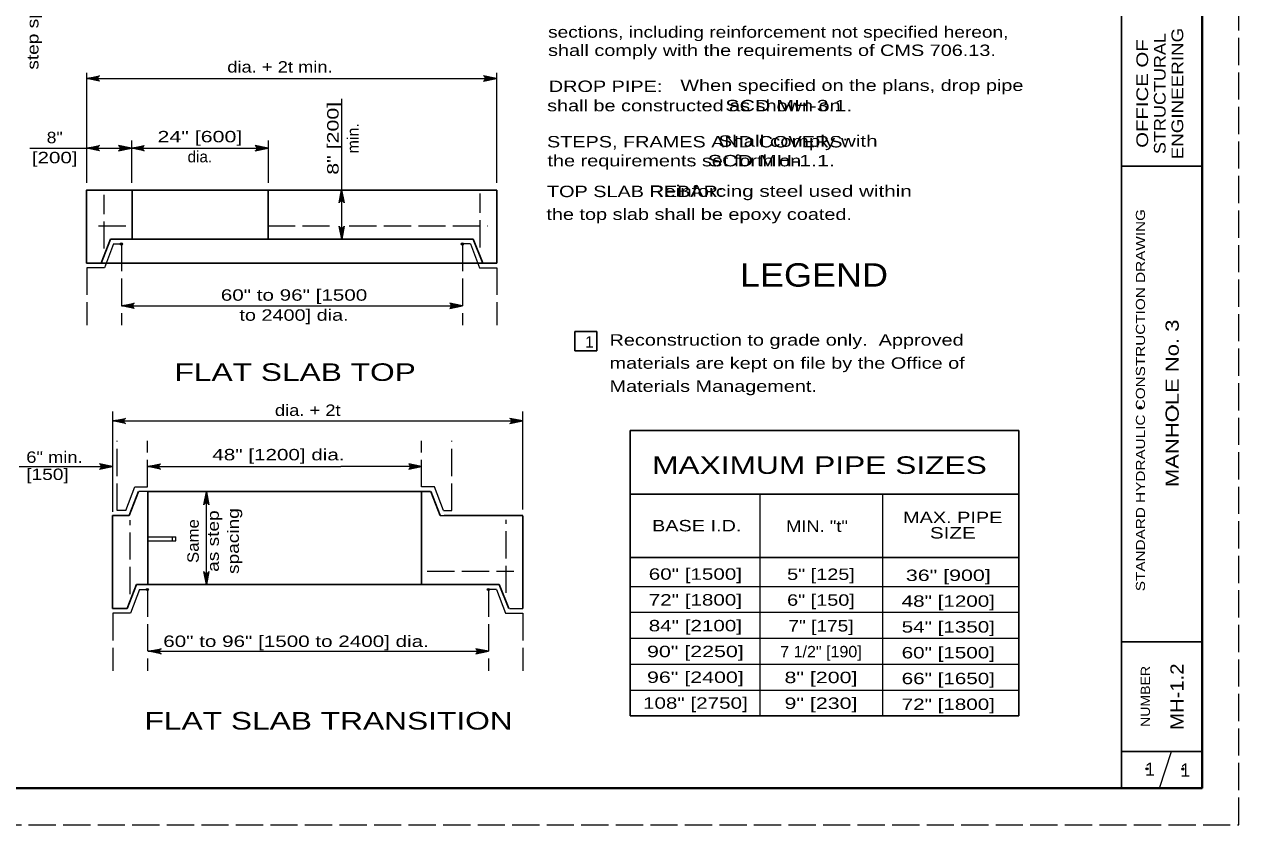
# Model space of a CAD drawing. Extents: x 808.4 to 842.4, y 1034.6 to 1056.6.
# Drawn here: x 825.84 to 842.44, y 1034.63 to 1045.57 of the extents above; entities that cross this region are included whole.
import ezdxf
from ezdxf.enums import TextEntityAlignment as Align

# ---------------------------------------------------------------- set-up
doc = ezdxf.new("R2010")
doc.units = 0
doc.header["$LTSCALE"] = 0.062
doc.header["$PDMODE"] = 32
doc.header["$PDSIZE"] = 0.031
doc.linetypes.add('LONG_DASHED', pattern=[7.5, 6, -1.5])
doc.layers.add('1', color=7, linetype='Continuous', lineweight=13)
doc.layers.add('10', color=7, linetype='Continuous')

msp = doc.modelspace()

# ---------------------------------------------------------------- linework, layer by layer
at = {"layer": '1', "lineweight": 25}
for p, q in [((840.83883, 1035.12767), (840.83883, 1056.12767)), ((841.93883, 1043.62767), (840.83883, 1043.62767)), ((827.31842, 1043.30192), (827.31842, 1042.64233)), ((829.17775, 1043.29608), (829.17775, 1042.6365)), ((832.30142, 1042.30433), (832.30142, 1043.30375)), ((827.0205, 1042.63308), (826.89208, 1042.30433)), ((827.0205, 1042.63308), (826.89208, 1042.30433)), ((827.0205, 1042.63308), (831.979, 1042.63308)), ((831.979, 1042.63308), (832.10733, 1042.30433)), ((826.69408, 1042.30433), (830.24717, 1042.30433)), ((830.24717, 1042.30433), (832.30142, 1042.30433)), ((834.12375, 1036.11517), (834.12375, 1040.01483)), ((834.12375, 1040.01483), (839.43508, 1040.01483)), ((839.43508, 1040.01483), (839.43508, 1036.11517)), ((827.27517, 1038.85458), (827.40358, 1039.18325)), ((827.5325, 1039.18325), (827.5325, 1038.624)), ((827.5325, 1039.18325), (828.22292, 1039.18325)), ((828.20442, 1039.18325), (831.39317, 1039.18325)), ((831.26942, 1039.18325), (831.26942, 1038.26033)), ((831.52533, 1038.85458), (831.397, 1039.18325)), ((834.12375, 1039.14483), (839.43508, 1039.14483)), ((827.27517, 1038.85458), (827.04642, 1038.85458)), ((827.04958, 1038.624), (827.04958, 1038.85533)), ((831.57933, 1038.85458), (832.65692, 1038.85458)), ((832.65692, 1038.624), (832.65692, 1038.85225)), ((827.04958, 1037.58108), (827.04958, 1038.66317)), ((827.5325, 1038.65608), (827.5325, 1037.91908)), ((832.65692, 1037.58108), (832.65692, 1038.624)), ((831.26942, 1038.28175), (831.26942, 1037.91908)), ((834.12517, 1038.2785), (839.43508, 1038.2785)), ((827.37592, 1037.90983), (827.24758, 1037.58108)), ((827.37592, 1037.90983), (827.24758, 1037.58108)), ((827.37592, 1037.90983), (832.33442, 1037.90983)), ((832.33442, 1037.90983), (832.46283, 1037.58108)), ((827.04958, 1037.58108), (827.25, 1037.58108)), ((841.93883, 1037.12767), (840.83883, 1037.12767)), ((834.12375, 1036.11517), (839.43508, 1036.11517)), ((841.93883, 1035.62767), (840.83883, 1035.62767))]:
    msp.add_line(p, q, dxfattribs=at)
at = {"layer": '1'}
for p, q in [((826.69433, 1044.907), (826.69433, 1043.4005)), ((832.29692, 1044.907), (832.29692, 1043.4005)), ((826.85308, 1044.85108), (826.69283, 1044.82867)), ((826.84767, 1044.83992), (826.69283, 1044.82867)), ((826.69283, 1044.82867), (830.56875, 1044.82867)), ((826.846, 1044.82867), (826.69283, 1044.82867)), ((826.84883, 1044.81425), (826.69283, 1044.82867)), ((826.85492, 1044.80383), (826.69283, 1044.82867)), ((830.56875, 1044.82867), (832.29692, 1044.82867)), ((832.13483, 1044.80383), (832.29692, 1044.82867)), ((832.13675, 1044.85108), (832.29692, 1044.82867)), ((832.141, 1044.81425), (832.29692, 1044.82867)), ((832.14217, 1044.83992), (832.29692, 1044.82867)), ((832.14375, 1044.82867), (832.29692, 1044.82867)), ((830.18075, 1042.63308), (830.18075, 1044.55125)), ((826.85483, 1043.89825), (826.69458, 1043.87583)), ((826.84933, 1043.88717), (826.69458, 1043.87583)), ((827.14617, 1043.898), (827.30642, 1043.87558)), ((827.15158, 1043.88692), (827.30642, 1043.87558)), ((827.30633, 1043.97975), (827.30633, 1043.4005)), ((827.46667, 1043.898), (827.30642, 1043.87558)), ((827.46125, 1043.88692), (827.30642, 1043.87558)), ((829.01467, 1043.898), (829.17483, 1043.8755)), ((829.02008, 1043.88683), (829.17483, 1043.8755)), ((829.17558, 1043.97975), (829.17558, 1043.4005)), ((825.91942, 1043.87558), (827.32025, 1043.87558)), ((826.84775, 1043.87583), (826.69458, 1043.87583)), ((826.85058, 1043.86142), (826.69458, 1043.87583)), ((826.85667, 1043.851), (826.69458, 1043.87583)), ((827.14433, 1043.85083), (827.30642, 1043.87558)), ((827.15042, 1043.86117), (827.30642, 1043.87558)), ((827.15325, 1043.87558), (827.30642, 1043.87558)), ((827.45958, 1043.87558), (827.30642, 1043.87558)), ((827.46242, 1043.86117), (827.30642, 1043.87558)), ((827.46858, 1043.85083), (827.30642, 1043.87558)), ((829.01275, 1043.85075), (829.17483, 1043.8755)), ((829.01892, 1043.86117), (829.17483, 1043.8755)), ((829.02167, 1043.8755), (829.17483, 1043.8755)), ((830.15517, 1043.1455), (830.18, 1043.30758)), ((830.16558, 1043.15167), (830.18, 1043.30758)), ((830.18, 1043.15442), (830.18, 1043.30758)), ((830.19133, 1043.15283), (830.18, 1043.30758)), ((830.20242, 1043.14742), (830.18, 1043.30758)), ((830.15833, 1042.79283), (830.18075, 1042.63258)), ((830.16942, 1042.78733), (830.18075, 1042.63258)), ((830.2055, 1042.79467), (830.18075, 1042.63258)), ((830.19517, 1042.78858), (830.18075, 1042.63258)), ((830.18075, 1042.78575), (830.18075, 1042.63258)), ((830.18075, 1042.63308), (830.18075, 1042.63258)), ((827.32967, 1041.74367), (827.16942, 1041.72125)), ((827.32417, 1041.73258), (827.16942, 1041.72125)), ((827.16942, 1041.72125), (830.75725, 1041.72125)), ((827.32258, 1041.72125), (827.16942, 1041.72125)), ((827.32542, 1041.70683), (827.16942, 1041.72125)), ((827.3315, 1041.6965), (827.16942, 1041.72125)), ((830.75725, 1041.72125), (831.83308, 1041.72125)), ((831.67092, 1041.6965), (831.83308, 1041.72125)), ((831.67283, 1041.74367), (831.83308, 1041.72125)), ((831.67708, 1041.70683), (831.83308, 1041.72125)), ((831.67825, 1041.73258), (831.83308, 1041.72125)), ((831.67992, 1041.72125), (831.83308, 1041.72125)), ((827.04975, 1040.27833), (827.04975, 1038.90517)), ((832.65242, 1040.27833), (832.65242, 1038.93592)), ((827.21, 1040.16908), (827.04975, 1040.14667)), ((827.20458, 1040.158), (827.04975, 1040.14667)), ((827.04975, 1040.14667), (830.62492, 1040.14667)), ((827.20292, 1040.14667), (827.04975, 1040.14667)), ((827.20575, 1040.13225), (827.04975, 1040.14667)), ((827.21192, 1040.12183), (827.04975, 1040.14667)), ((830.62492, 1040.14667), (832.65408, 1040.14667)), ((832.49192, 1040.12183), (832.65408, 1040.14667)), ((832.49383, 1040.16908), (832.65408, 1040.14667)), ((832.49808, 1040.13225), (832.65408, 1040.14667)), ((832.49925, 1040.158), (832.65408, 1040.14667)), ((832.50092, 1040.14667), (832.65408, 1040.14667)), ((825.77383, 1039.52317), (827.04975, 1039.52317)), ((826.88767, 1039.49842), (827.04975, 1039.52317)), ((826.8895, 1039.54558), (827.04975, 1039.52317)), ((826.89375, 1039.50875), (827.04975, 1039.52317)), ((826.895, 1039.5345), (827.04975, 1039.52317)), ((826.89658, 1039.52317), (827.04975, 1039.52317)), ((827.68767, 1039.54558), (827.52742, 1039.52317)), ((827.68225, 1039.5345), (827.52742, 1039.52317)), ((827.52742, 1039.52317), (830.16733, 1039.52317)), ((827.68058, 1039.52317), (827.52742, 1039.52317)), ((827.68342, 1039.50875), (827.52742, 1039.52317)), ((827.68958, 1039.49842), (827.52742, 1039.52317)), ((831.27308, 1039.52317), (830.16733, 1039.52317)), ((831.11092, 1039.49842), (831.27308, 1039.52317)), ((831.11283, 1039.54558), (831.27308, 1039.52317)), ((831.11708, 1039.50875), (831.27308, 1039.52317)), ((831.11825, 1039.5345), (831.27308, 1039.52317)), ((831.11992, 1039.52317), (831.27308, 1039.52317)), ((827.5325, 1039.18325), (827.4065, 1039.18325)), ((828.30658, 1039.01658), (828.33133, 1039.17867)), ((828.31692, 1039.02267), (828.33133, 1039.17867)), ((828.33133, 1037.90983), (828.33133, 1039.17867)), ((828.33133, 1039.0255), (828.33133, 1039.17867)), ((828.34267, 1039.02392), (828.33133, 1039.17867)), ((828.35375, 1039.0185), (828.33133, 1039.17867)), ((831.26808, 1039.18325), (831.39408, 1039.18325)), ((835.89375, 1039.13467), (835.89375, 1036.11517)), ((837.57075, 1039.13467), (837.57075, 1036.11517)), ((831.52533, 1038.85458), (831.75417, 1038.85458)), ((827.53442, 1038.563), (827.9125, 1038.563)), ((827.53442, 1038.51), (827.9125, 1038.51)), ((827.86875, 1038.50917), (827.86875, 1038.56217)), ((827.9125, 1038.51), (827.9125, 1038.563)), ((828.30892, 1038.07008), (828.33133, 1037.90983)), ((828.35608, 1038.072), (828.33133, 1037.90983)), ((828.32, 1038.06467), (828.33133, 1037.90983)), ((828.34575, 1038.06583), (828.33133, 1037.90983)), ((828.33133, 1038.063), (828.33133, 1037.90983)), ((834.12517, 1037.88517), (839.43508, 1037.88517)), ((832.4745, 1037.58108), (832.65692, 1037.58108)), ((834.12517, 1037.53117), (839.43508, 1037.53117)), ((834.12517, 1037.17717), (839.43508, 1037.17717)), ((827.69475, 1037.0205), (827.5345, 1036.99808)), ((827.68933, 1037.00933), (827.5345, 1036.99808)), ((827.5345, 1036.99808), (831.12242, 1036.99808)), ((827.68767, 1036.99808), (827.5345, 1036.99808)), ((827.6905, 1036.98367), (827.5345, 1036.99808)), ((827.69667, 1036.97325), (827.5345, 1036.99808)), ((831.12242, 1036.99808), (832.1885, 1036.99808)), ((832.02642, 1036.97325), (832.1885, 1036.99808)), ((832.02825, 1037.0205), (832.1885, 1036.99808)), ((832.0325, 1036.98367), (832.1885, 1036.99808)), ((832.03375, 1037.00933), (832.1885, 1036.99808)), ((832.03533, 1036.99808), (832.1885, 1036.99808)), ((834.12517, 1036.82317), (839.43508, 1036.82317)), ((834.12375, 1036.46917), (839.43508, 1036.46917)), ((834.12517, 1036.46917), (839.43508, 1036.46917)), ((841.3555, 1035.12767), (841.52217, 1035.62767))]:
    msp.add_line(p, q, dxfattribs=at)
at = {"layer": '1', "linetype": 'LONG_DASHED'}
for p, q in [((826.93425, 1042.50267), (826.93425, 1043.23833)), ((832.07308, 1042.51867), (832.07308, 1043.25425)), ((826.85767, 1042.81542), (827.317, 1042.81542)), ((829.17092, 1042.81542), (830.10125, 1042.81542)), ((830.28408, 1042.81542), (832.17917, 1042.81542)), ((827.06, 1042.56633), (826.93708, 1042.24142)), ((831.93942, 1042.56633), (831.83008, 1042.56633)), ((831.83008, 1042.56633), (831.83008, 1041.45425)), ((831.93942, 1042.56633), (832.06233, 1042.24142)), ((827.11375, 1038.92125), (827.11375, 1039.87725)), ((827.52742, 1039.24567), (827.52742, 1039.87725)), ((831.27308, 1039.24567), (831.27308, 1039.87725)), ((831.68683, 1038.92125), (831.68683, 1039.87725)), ((827.22958, 1038.92075), (827.35258, 1039.24567)), ((827.35258, 1039.24567), (827.52742, 1039.24567)), ((831.448, 1039.24567), (831.27308, 1039.24567)), ((831.57092, 1038.92075), (831.448, 1039.24567)), ((827.23067, 1038.92125), (827.11375, 1038.92125)), ((831.56992, 1038.92125), (831.68683, 1038.92125)), ((827.28975, 1037.77942), (827.28975, 1038.79158)), ((832.4285, 1037.79542), (832.4285, 1038.79517)), ((831.35017, 1038.09225), (832.53467, 1038.09225)), ((827.4155, 1037.84317), (827.29258, 1037.51825)), ((832.29492, 1037.84317), (832.1855, 1037.84317)), ((832.1855, 1037.84317), (832.1855, 1036.731)), ((832.29492, 1037.84317), (832.41783, 1037.51825))]:
    msp.add_line(p, q, dxfattribs=at)
msp.add_lwpolyline([(808.43883, 1034.62767), (842.43883, 1034.62767), (842.43883, 1056.62767), (808.43883, 1056.62767)], close=True, dxfattribs=at)
at = {"layer": '1', "lineweight": 25}
for points in [[(810.43883, 1056.12767), (841.93883, 1056.12767), (841.93883, 1035.12767), (810.43883, 1035.12767)], [(833.36825, 1041.36917), (833.36825, 1041.10758), (833.66683, 1041.10758), (833.66683, 1041.36917)]]:
    msp.add_lwpolyline(points, close=True, dxfattribs=at)
at = {"layer": '1', "lineweight": 40}
msp.add_lwpolyline([(810.43883, 1056.12767), (841.93883, 1056.12767), (841.93883, 1035.12767), (810.43883, 1035.12767)], close=True, dxfattribs=at)
at = {"layer": '1'}
for points in [[(826.86983, 1044.79325), (826.69283, 1044.82867), (826.86983, 1044.864)], [(832.11992, 1044.79325), (832.29692, 1044.82867), (832.11992, 1044.864)], [(826.87158, 1043.84042), (826.69458, 1043.87583), (826.87158, 1043.91125)], [(827.12942, 1043.84017), (827.30642, 1043.87558), (827.12942, 1043.911)], [(827.48342, 1043.84017), (827.30642, 1043.87558), (827.48342, 1043.911)], [(828.99783, 1043.84017), (829.17483, 1043.8755), (828.99783, 1043.91092)], [(827.32025, 1043.87558), (828.80433, 1043.87558), (829.17558, 1043.87558)], [(830.14458, 1043.13058), (830.18, 1043.30758), (830.21542, 1043.13058)], [(830.21617, 1042.80958), (830.18075, 1042.63258), (830.14533, 1042.80958)], [(827.34642, 1041.68583), (827.16942, 1041.72125), (827.34642, 1041.75667)], [(831.65608, 1041.68583), (831.83308, 1041.72125), (831.65608, 1041.75667)], [(827.22675, 1040.11125), (827.04975, 1040.14667), (827.22675, 1040.18208)], [(832.47708, 1040.11125), (832.65408, 1040.14667), (832.47708, 1040.18208)], [(826.87275, 1039.48775), (827.04975, 1039.52317), (826.87275, 1039.55858)], [(827.70442, 1039.48775), (827.52742, 1039.52317), (827.70442, 1039.55858)], [(831.09608, 1039.48775), (831.27308, 1039.52317), (831.09608, 1039.55858)], [(828.29592, 1039.00167), (828.33133, 1039.17867), (828.36675, 1039.00167)], [(828.36675, 1038.08683), (828.33133, 1037.90983), (828.29592, 1038.08683)], [(827.7115, 1036.96267), (827.5345, 1036.99808), (827.7115, 1037.03342)], [(832.0115, 1036.96267), (832.1885, 1036.99808), (832.0115, 1037.03342)]]:
    msp.add_lwpolyline(points, dxfattribs=at)
at = {"layer": '1', "lineweight": 25}
msp.add_lwpolyline([(826.69408, 1042.30433), (826.69408, 1043.30375), (832.30142, 1043.30375)], dxfattribs=at)
at = {"layer": '1', "linetype": 'LONG_DASHED'}
for points in [[(827.06, 1042.56633), (827.16942, 1042.56633), (827.16942, 1041.45425)], [(826.93708, 1042.24192), (826.69908, 1042.24192), (826.69908, 1041.45425)], [(832.06233, 1042.24192), (832.30033, 1042.24192), (832.30033, 1041.45425)], [(827.4155, 1037.84317), (827.52483, 1037.84317), (827.52483, 1036.731)], [(827.29258, 1037.51875), (827.05458, 1037.51875), (827.05458, 1036.731)], [(832.41783, 1037.51875), (832.65583, 1037.51875), (832.65583, 1036.731)]]:
    msp.add_lwpolyline(points, dxfattribs=at)
at = {"layer": '1'}
for centre, start, end in [((826.88412, 1044.82867), 112.08782, 247.91395), ((832.10566, 1044.82867), 292.08605, 67.91218), ((826.88584, 1043.87585), 112.08782, 247.91395), ((827.11514, 1043.87563), 292.08605, 67.91218), ((827.49772, 1043.87563), 112.08782, 247.91395), ((828.98358, 1043.87558), 292.08605, 67.91218), ((830.18003, 1043.11633), 22.08782, 157.91395), ((830.1807, 1042.82385), 202.08782, 337.91395), ((827.36068, 1041.72129), 112.08782, 247.91395), ((831.64176, 1041.72129), 292.08605, 67.91218), ((827.24108, 1040.14668), 112.08782, 247.91395), ((832.46278, 1040.14668), 292.08605, 67.91218), ((826.85849, 1039.52321), 292.08605, 67.91218), ((827.71874, 1039.52321), 112.08782, 247.91395), ((831.08179, 1039.52321), 292.08605, 67.91218), ((828.33138, 1038.98741), 22.08782, 157.91395), ((828.3313, 1038.10114), 202.08782, 337.91395), ((827.72582, 1036.99808), 112.08782, 247.91395), ((831.99723, 1036.99808), 292.08605, 67.91218)]:
    msp.add_arc(centre, 0.0382, start, end, dxfattribs=at)
for p in [(827.16942, 1042.56633), (831.83008, 1042.56633), (841.09625, 1040.33367), (841.52908, 1040.341), (827.52483, 1037.84317), (832.1855, 1037.84317), (841.18692, 1035.39142), (841.67533, 1035.39042)]:
    msp.add_point(p, dxfattribs=at)

# ---------------------------------------------------------------- texts
for s, height, width, p in [('STRUCTURAL', 0.16, 1.15, (841.44058, 1044.62212)), ('ENGINEERING', 0.16, 1.2, (841.68058, 1044.62221)), ('OFFICE OF', 0.16, 1.3, (841.20058, 1044.62212)), ('STANDARD HYDRAULIC CONSTRUCTION DRAWING', 0.125, 1.25, (841.15875, 1040.43171)), ('MANHOLE No. 3', 0.18, 1.25, (841.61925, 1040.38783)), ('NUMBER', 0.125, 1.15, (841.22583, 1036.38175)), ('MH-1.2', 0.18, 1.15, (841.68492, 1036.37796))]:
    msp.add_text(s, height=height, rotation=90, dxfattribs=dict(at, width=width)).set_placement(p, align=Align.CENTER)
msp.add_text('1', height=0.156, dxfattribs=at).set_placement((833.507, 1041.14992))
for s, width, p in [('5" [125]', 1.3, (836.73021, 1037.97358)), ('36" [900]', 1.4, (838.47017, 1037.95925)), ('6" [150]', 1.3, (836.73025, 1037.62092)), ('48" [1200]', 1.35, (838.47017, 1037.60658)), ('7" [175]', 1.25, (836.73029, 1037.26825)), ('54" [1350]', 1.35, (838.47017, 1037.25392)), ('7 1/2" [190]', 1.05, (836.73025, 1036.91558)), ('60" [1500]', 1.35, (838.47021, 1036.90125)), ('8" [200]', 1.4, (836.73021, 1036.56292)), ('66" [1650]', 1.35, (838.47021, 1036.54858)), ('9" [230]', 1.4, (836.73021, 1036.21025)), ('72" [1800]', 1.35, (838.47021, 1036.19592))]:
    msp.add_text(s, height=0.156, dxfattribs=dict(at, width=width)).set_placement(p, align=Align.CENTER)
for p in [(841.22668, 1035.29775), (841.70952, 1035.28517)]:
    msp.add_text('1', height=0.18, dxfattribs=at).set_placement(p, align=Align.CENTER)
at = {"layer": '10'}
for s, width, p in [('step spacing', 1.25, (826.03675, 1045.68096)), ('8" [200]', 1.4, (830.138, 1044.01071)), ('min.', 1.05, (830.412, 1044.01075)), ('as step', 1.25, (828.50142, 1038.50492)), ('spacing', 1.25, (828.77542, 1038.50487)), ('Same', 1.1, (828.22742, 1038.50496))]:
    msp.add_text(s, height=0.156, rotation=90, dxfattribs=dict(at, width=width)).set_placement(p, align=Align.CENTER)
for s, height, width, p in [('sections, including reinforcement not specified hereon,', 0.156, 1.25, (833.00092, 1045.38567)), ('shall comply with the requirements of CMS 706.13.', 0.156, 1.3, (833.00092, 1045.13583)), ('dia. + 2t min.', 0.156, 1.2, (828.61708, 1044.90933)), ('DROP PIPE:', 0.156, 1.3, (833.01067, 1044.64367)), ('When specified on the plans, drop pipe', 0.156, 1.3, (834.80817, 1044.65708)), ('shall be constructed as shown on', 0.156, 1.3, (832.98817, 1044.37975)), ('                              SCD MH-3.1.', 0.156, 1.4, (832.98817, 1044.37975)), ('STEPS, FRAMES AND COVERS:', 0.156, 1.3, (832.98558, 1043.88608)), ('                          Shall comply with', 0.156, 1.35, (833.294, 1043.89525)), ('the requirements set forth on', 0.156, 1.3, (832.99283, 1043.627)), ('                           SCD MH-1.1.', 0.156, 1.4, (832.99283, 1043.627)), ('TOP SLAB REBAR:', 0.156, 1.3, (832.98558, 1043.20675)), ('                  Reinforcing steel used within ', 0.156, 1.35, (832.97767, 1043.21067)), ('the top slab shall be epoxy coated. ', 0.156, 1.3, (832.97767, 1042.89467)), ('Reconstruction to grade only.  Approved ', 0.156, 1.3, (833.84083, 1041.1765)), ('FLAT SLAB TOP', 0.24, 1.35, (827.89542, 1040.69417)), ('materials are kept on file by the Office of', 0.156, 1.3, (833.84083, 1040.8605)), ('Materials Management.', 0.156, 1.3, (833.84083, 1040.5445)), ('dia. + 2t', 0.156, 1.2, (829.26758, 1040.21592)), ('6" min.', 0.156, 1.2, (825.87017, 1039.57433)), ('48" [1200] dia. ', 0.156, 1.35, (828.41283, 1039.6085)), ('MAXIMUM PIPE SIZES', 0.24, 1.35, (834.42217, 1039.42292)), ('[150]', 0.156, 1.25, (825.87017, 1039.33967)), ('MAX. PIPE', 0.156, 1.3, (837.85258, 1038.7505)), ('BASE I.D.', 0.156, 1.3, (834.42183, 1038.63758)), ('MIN. "t"', 0.156, 1.2, (836.25333, 1038.63042)), ('SIZE', 0.156, 1.35, (838.21908, 1038.53975)), ('60" to 96" [1500 to 2400] dia. ', 0.156, 1.35, (827.74192, 1037.05742)), ('FLAT SLAB TRANSITION', 0.24, 1.35, (827.48608, 1035.92817))]:
    msp.add_text(s, height=height, dxfattribs=dict(at, width=width)).set_placement(p)
for s, height, width, p in [('8"', 0.156, 1.15, (826.2585, 1043.94342)), ('24" [600]', 0.156, 1.4, (828.24279, 1043.95575)), ('[200]', 0.156, 1.35, (826.2585, 1043.66942)), ('LEGEND', 0.32, 1.15, (836.63458, 1041.9825)), ('60" to 96" [1500', 0.156, 1.35, (829.52904, 1041.7905)), ('to 2400] dia.', 0.156, 1.3, (829.529, 1041.5165)), ('60" [1500]', 0.156, 1.35, (835.01387, 1037.97633)), ('72" [1800]', 0.156, 1.35, (835.01387, 1037.62367)), ('84" [2100]', 0.156, 1.35, (835.01383, 1037.271)), ('90" [2250]', 0.156, 1.4, (835.01383, 1036.91833)), ('96" [2400]', 0.156, 1.4, (835.01379, 1036.56567)), ('108" [2750]', 0.156, 1.35, (835.01379, 1036.213))]:
    msp.add_text(s, height=height, dxfattribs=dict(at, width=width)).set_placement(p, align=Align.CENTER)
msp.add_text('dia.', height=0.156, dxfattribs=at).set_placement((828.24279, 1043.68175), align=Align.CENTER)

doc.saveas('drawing.dxf')
